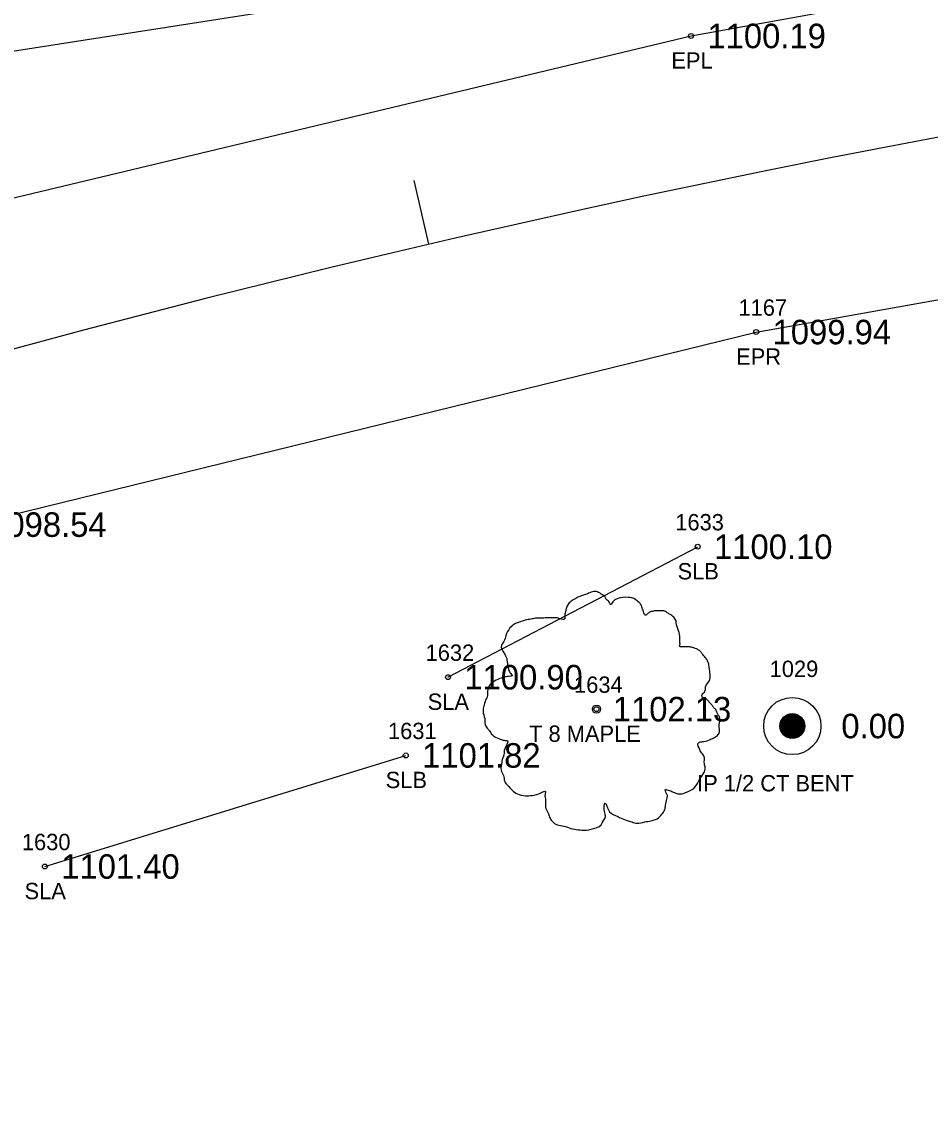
# Model space of a CAD drawing. Extents: x 1539151 to 1541799, y 1198646 to 1201165.
# Drawn here: x 1541156.3 to 1541211.9, y 1200361.6 to 1200427.6 of the extents above; entities that cross this region are included whole.
import ezdxf

# ---------------------------------------------------------------- set-up
doc = ezdxf.new("R2010")
doc.units = 0
for name, color, linetype in [('RD_EX_DV_Prop_txCode', 7, 'Continuous'), ('RD_EX_DV_PropPin', 7, 'Continuous'), ('RD_EX_Road', 7, 'Continuous'), ('RD_EX_Road_txCode', 7, 'Continuous'), ('RD_EX_TX_DV_Prop_ELEV', 7, 'Continuous'), ('RD_EX_TX_Road_ELEV', 7, 'Continuous'), ('RD_EX_TX_VEG_ELEV', 7, 'Continuous'), ('RD_EX_VEG', 7, 'Continuous'), ('RD_EX_VEG_txCode', 7, 'Continuous'), ('RD_HC_Cl', 7, 'Continuous'), ('RD_HC_Data_Tic', 7, 'Continuous'), ('RD_SMD_Locator', 7, 'Continuous')]:
    doc.layers.add(name, color=color, linetype=linetype)

msp = doc.modelspace()

# ---------------------------------------------------------------- linework, layer by layer
at = {"layer": 'RD_EX_DV_PropPin'}
for p, q in [((1541202.826, 1200384.064), (1541202.826, 1200385.012)), ((1541202.861, 1200384.023), (1541202.861, 1200385.053)), ((1541202.896, 1200383.987), (1541202.896, 1200385.089)), ((1541202.931, 1200383.956), (1541202.931, 1200385.12)), ((1541202.966, 1200383.928), (1541202.966, 1200385.148)), ((1541203.001, 1200383.903), (1541203.001, 1200385.172)), ((1541203.036, 1200383.881), (1541203.036, 1200385.194)), ((1541203.071, 1200383.862), (1541203.071, 1200385.213)), ((1541203.106, 1200383.845), (1541203.106, 1200385.231)), ((1541203.141, 1200383.83), (1541203.141, 1200385.245)), ((1541203.176, 1200383.817), (1541203.176, 1200385.258)), ((1541203.211, 1200383.806), (1541203.211, 1200385.269)), ((1541203.246, 1200383.797), (1541203.246, 1200385.278)), ((1541203.281, 1200383.79), (1541203.281, 1200385.286)), ((1541203.316, 1200383.784), (1541203.316, 1200385.292)), ((1541203.351, 1200383.78), (1541203.351, 1200385.296)), ((1541203.386, 1200383.778), (1541203.386, 1200385.298)), ((1541203.421, 1200383.777), (1541203.421, 1200385.299)), ((1541203.456, 1200383.778), (1541203.456, 1200385.298)), ((1541203.491, 1200383.78), (1541203.491, 1200385.296)), ((1541203.526, 1200383.784), (1541203.526, 1200385.292)), ((1541203.561, 1200383.79), (1541203.561, 1200385.286)), ((1541203.596, 1200383.797), (1541203.596, 1200385.278)), ((1541203.631, 1200383.806), (1541203.631, 1200385.269)), ((1541203.666, 1200383.817), (1541203.666, 1200385.258)), ((1541203.701, 1200383.83), (1541203.701, 1200385.245)), ((1541203.736, 1200383.845), (1541203.736, 1200385.231)), ((1541203.771, 1200383.862), (1541203.771, 1200385.213)), ((1541203.806, 1200383.881), (1541203.806, 1200385.194)), ((1541203.841, 1200383.903), (1541203.841, 1200385.172)), ((1541203.876, 1200383.928), (1541203.876, 1200385.148)), ((1541203.911, 1200383.956), (1541203.911, 1200385.12)), ((1541203.946, 1200383.987), (1541203.946, 1200385.089)), ((1541203.981, 1200384.023), (1541203.981, 1200385.053)), ((1541204.016, 1200384.064), (1541204.016, 1200385.012)), ((1541202.686, 1200384.342), (1541202.686, 1200384.734)), ((1541202.721, 1200384.24), (1541202.721, 1200384.836)), ((1541202.756, 1200384.168), (1541202.756, 1200384.907)), ((1541202.791, 1200384.111), (1541202.791, 1200384.964)), ((1541204.051, 1200384.111), (1541204.051, 1200384.964)), ((1541204.086, 1200384.168), (1541204.086, 1200384.907)), ((1541204.121, 1200384.24), (1541204.121, 1200384.836)), ((1541204.156, 1200384.342), (1541204.156, 1200384.734))]:
    msp.add_line(p, q, dxfattribs=at)
for radius in [1.75, 0.761]:
    msp.add_circle((1541203.421, 1200384.538), radius, dxfattribs=at)
at = {"layer": 'RD_EX_Road'}
for points in [[(1540705.322, 1200094.038), (1540739.01, 1200131.561), (1540770.497, 1200167.373), (1540805.537, 1200205.845), (1540841.216, 1200241.631), (1540879.368, 1200275.734), (1540919.786, 1200306.259), (1540962.727, 1200334.431), (1541008.04, 1200359.974), (1541051.863, 1200381.288), (1541099.365, 1200400.025), (1541147.987, 1200415.009), (1541197.225, 1200426.761), (1541247.293, 1200435.809)], [(1540718.68, 1200081.327), (1540762.243, 1200130.195), (1540779.722, 1200149.92), (1540818.991, 1200193.085), (1540844.694, 1200219.089), (1540861.587, 1200235.219), (1540891.57, 1200261.374), (1540930.279, 1200290.778), (1540971.824, 1200318.199), (1541015.093, 1200342.794), (1541060.357, 1200364.795), (1541076.533, 1200371.562), (1541099.096, 1200380.088), (1541153.211, 1200396.862), (1541201.214, 1200408.644), (1541249.91, 1200417.319)]]:
    msp.add_lwpolyline(points, dxfattribs=at)
at = {"layer": 'RD_EX_VEG'}
for p, q in [((1541182.351, 1200387.526), (1541197.629, 1200395.509)), ((1541157.685, 1200375.942), (1541179.767, 1200382.74))]:
    msp.add_line(p, q, dxfattribs=at)
msp.add_lwpolyline([(1541184.888, 1200430.38), (1541110.905, 1200418.834), (1540957.415, 1200347.719), (1540870.985, 1200282.613), (1540802.214, 1200226.224), (1540781.044, 1200235.771)], dxfattribs=at)
for centre, radius in [((1541191.435, 1200385.57), 0.25), ((1541191.423, 1200385.551), 0.0001)]:
    msp.add_circle(centre, radius, dxfattribs=at)
for points in [[(1541191.567, 1200392.737), (1541191.267, 1200392.762), (1541190.943, 1200392.662), (1541190.693, 1200392.562), (1541190.468, 1200392.487), (1541190.243, 1200392.387), (1541189.943, 1200392.212), (1541189.718, 1200392.012), (1541189.593, 1200391.762), (1541189.543, 1200391.537), (1541189.493, 1200391.262), (1541189.493, 1200391.087), (1541189.368, 1200391.062), (1541189.218, 1200391.087), (1541188.968, 1200391.162), (1541188.718, 1200391.162), (1541188.469, 1200391.162), (1541188.119, 1200391.137), (1541187.769, 1200391.137), (1541187.494, 1200391.087), (1541187.169, 1200391.038), (1541186.794, 1200390.913), (1541186.444, 1200390.788), (1541186.145, 1200390.538), (1541185.895, 1200390.063), (1541185.77, 1200389.713), (1541185.62, 1200389.463), (1541185.77, 1200389.013), (1541185.945, 1200388.664), (1541185.97, 1200388.464), (1541186.045, 1200388.039), (1541186.145, 1200387.814), (1541186.27, 1200387.614), (1541186.195, 1200387.589), (1541185.82, 1200387.539), (1541185.52, 1200387.439), (1541185.095, 1200387.214), (1541184.87, 1200386.989), (1541184.77, 1200386.664), (1541184.745, 1200386.315), (1541184.645, 1200386.115), (1541184.57, 1200385.84), (1541184.545, 1200385.765), (1541184.495, 1200385.44), (1541184.595, 1200384.99), (1541184.62, 1200384.64), (1541184.745, 1200384.415), (1541184.895, 1200384.241), (1541185.07, 1200383.991), (1541185.47, 1200383.766), (1541185.795, 1200383.666), (1541185.995, 1200383.641), (1541185.82, 1200383.141), (1541185.77, 1200382.791), (1541185.645, 1200382.391), (1541185.645, 1200382.316), (1541185.595, 1200381.842), (1541185.745, 1200381.517), (1541185.82, 1200381.142), (1541185.995, 1200380.917), (1541186.27, 1200380.617), (1541186.594, 1200380.392), (1541187.094, 1200380.267), (1541187.494, 1200380.292), (1541188.069, 1200380.467), (1541188.319, 1200380.542), (1541188.294, 1200380.367), (1541188.319, 1200379.992), (1541188.319, 1200379.568), (1541188.469, 1200379.243), (1541188.569, 1200378.968), (1541188.718, 1200378.718), (1541189.043, 1200378.493), (1541189.443, 1200378.418), (1541189.868, 1200378.268), (1541190.318, 1200378.193), (1541190.818, 1200378.168), (1541191.417, 1200378.318), (1541191.692, 1200378.443), (1541191.792, 1200378.618), (1541191.992, 1200378.993), (1541191.942, 1200379.218), (1541191.967, 1200379.817), (1541192.067, 1200379.642), (1541192.242, 1200379.293), (1541192.742, 1200378.993), (1541193.142, 1200378.818), (1541193.616, 1200378.668), (1541193.916, 1200378.593), (1541194.391, 1200378.668), (1541194.766, 1200378.743), (1541195.141, 1200378.868), (1541195.441, 1200379.143), (1541195.615, 1200379.418), (1541195.665, 1200379.692), (1541195.74, 1200380.067), (1541195.79, 1200380.242)], [(1541195.79, 1200380.242), (1541195.715, 1200380.417), (1541195.665, 1200380.667), (1541195.74, 1200380.642), (1541195.915, 1200380.592), (1541196.19, 1200380.467), (1541196.415, 1200380.392), (1541196.74, 1200380.417), (1541197.015, 1200380.517), (1541197.465, 1200380.792), (1541197.74, 1200381.267), (1541198.014, 1200381.667), (1541198.089, 1200381.991), (1541198.039, 1200382.216), (1541198.014, 1200382.716), (1541197.814, 1200382.966), (1541197.764, 1200383.091), (1541197.665, 1200383.491), (1541197.74, 1200383.541), (1541198.014, 1200383.591), (1541198.389, 1200383.716), (1541198.664, 1200383.841), (1541198.889, 1200384.016), (1541198.964, 1200384.241), (1541198.939, 1200384.64), (1541198.989, 1200385.04), (1541198.914, 1200385.19), (1541198.814, 1200385.34), (1541198.739, 1200385.54), (1541198.589, 1200385.69), (1541198.489, 1200385.84), (1541198.389, 1200385.94), (1541198.264, 1200386.09), (1541198.089, 1200386.215), (1541197.939, 1200386.265), (1541197.889, 1200386.415), (1541198.039, 1200386.614), (1541198.089, 1200386.714), (1541198.114, 1200386.939), (1541198.339, 1200387.289), (1541198.389, 1200387.689), (1541198.339, 1200388.114), (1541198.289, 1200388.389), (1541198.139, 1200388.664), (1541197.939, 1200388.913), (1541197.814, 1200389.088), (1541197.64, 1200389.213), (1541197.315, 1200389.338), (1541197.065, 1200389.388), (1541196.715, 1200389.388), (1541196.515, 1200389.438), (1541196.54, 1200389.488), (1541196.54, 1200389.638), (1541196.54, 1200389.913), (1541196.465, 1200390.363), (1541196.315, 1200390.863), (1541196.315, 1200390.888), (1541196.215, 1200391.137), (1541195.99, 1200391.337), (1541195.815, 1200391.437), (1541195.615, 1200391.562), (1541195.366, 1200391.587), (1541195.066, 1200391.587), (1541194.791, 1200391.537), (1541194.591, 1200391.437), (1541194.416, 1200391.312), (1541194.341, 1200391.462), (1541194.241, 1200391.762), (1541194.191, 1200391.912), (1541194.041, 1200392.087), (1541193.816, 1200392.287), (1541193.366, 1200392.412), (1541192.742, 1200392.337), (1541192.442, 1200392.137), (1541192.292, 1200391.962), (1541192.242, 1200392.087), (1541192.042, 1200392.287), (1541191.942, 1200392.462), (1541191.767, 1200392.587), (1541191.617, 1200392.687), (1541191.517, 1200392.737)]]:
    msp.add_spline(points, degree=3, dxfattribs=at)
at = {"layer": 'RD_HC_Cl'}
msp.add_arc((1541347.273, 1199701.685), 731.435, 99.312315, 138.327529, dxfattribs=at)
at = {"layer": 'RD_HC_Data_Tic'}
msp.add_line((1541181.188, 1200414.014), (1541180.28, 1200417.91), dxfattribs=at)
at = {"layer": 'RD_SMD_Locator'}
for centre in [(1541197.225, 1200426.761), (1541201.214, 1200408.644), (1541197.629, 1200395.509), (1541182.351, 1200387.526), (1541191.435, 1200385.57), (1541203.421, 1200384.538), (1541179.767, 1200382.74), (1541157.685, 1200375.942)]:
    msp.add_circle(centre, 0.15, dxfattribs=at)

# ---------------------------------------------------------------- texts
at = {"layer": 'RD_EX_DV_Prop_txCode'}
for s, p in [('1029', (1541202.035, 1200387.538)), ('IP 1/2 CT BENT', (1541197.594, 1200380.538))]:
    msp.add_text(s, height=1, dxfattribs=at).set_placement(p)
at = {"layer": 'RD_EX_Road_txCode'}
for s, p in [('EPL', (1541196.02, 1200424.761)), ('1167', (1541200.127, 1200409.644)), ('EPR', (1541199.985, 1200406.644))]:
    msp.add_text(s, height=1, dxfattribs=at).set_placement(p)
at = {"layer": 'RD_EX_TX_DV_Prop_ELEV'}
msp.add_text('0.00', height=1.5, dxfattribs=at).set_placement((1541206.421, 1200383.788))
at = {"layer": 'RD_EX_TX_Road_ELEV'}
for s, p in [('1100.19', (1541198.225, 1200426.011)), ('1099.94', (1541202.214, 1200407.894)), ('1098.54', (1541154.211, 1200396.112))]:
    msp.add_text(s, height=1.5, dxfattribs=at).set_placement(p)
at = {"layer": 'RD_EX_TX_VEG_ELEV'}
for s, p in [('1100.10', (1541198.629, 1200394.759)), ('1100.90', (1541183.351, 1200386.776)), ('1102.13', (1541192.435, 1200384.82)), ('1101.82', (1541180.767, 1200381.99)), ('1101.40', (1541158.685, 1200375.192))]:
    msp.add_text(s, height=1.5, dxfattribs=at).set_placement(p)
at = {"layer": 'RD_EX_VEG_txCode'}
for s, p in [('1633', (1541196.259, 1200396.509)), ('SLB', (1541196.401, 1200393.509)), ('1632', (1541180.981, 1200388.526)), ('1634', (1541190.065, 1200386.57)), ('SLA', (1541181.107, 1200385.526)), ('1631', (1541178.68, 1200383.74)), ('T 8 MAPLE', (1541187.313, 1200383.57)), ('SLB', (1541178.539, 1200380.74)), ('1630', (1541156.275, 1200376.942)), ('SLA', (1541156.441, 1200373.942))]:
    msp.add_text(s, height=1, dxfattribs=at).set_placement(p)

doc.saveas('drawing.dxf')
